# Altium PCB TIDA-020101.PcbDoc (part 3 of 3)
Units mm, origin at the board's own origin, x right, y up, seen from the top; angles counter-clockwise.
Board outline 55 x 55 mm, 4 copper layers (Top Layer 1, Top Layer, Bottom Layer, Bottom Layer 1), stack 1.647 mm thick; 151 components, 88 nets, 395 pads, 362 vias.
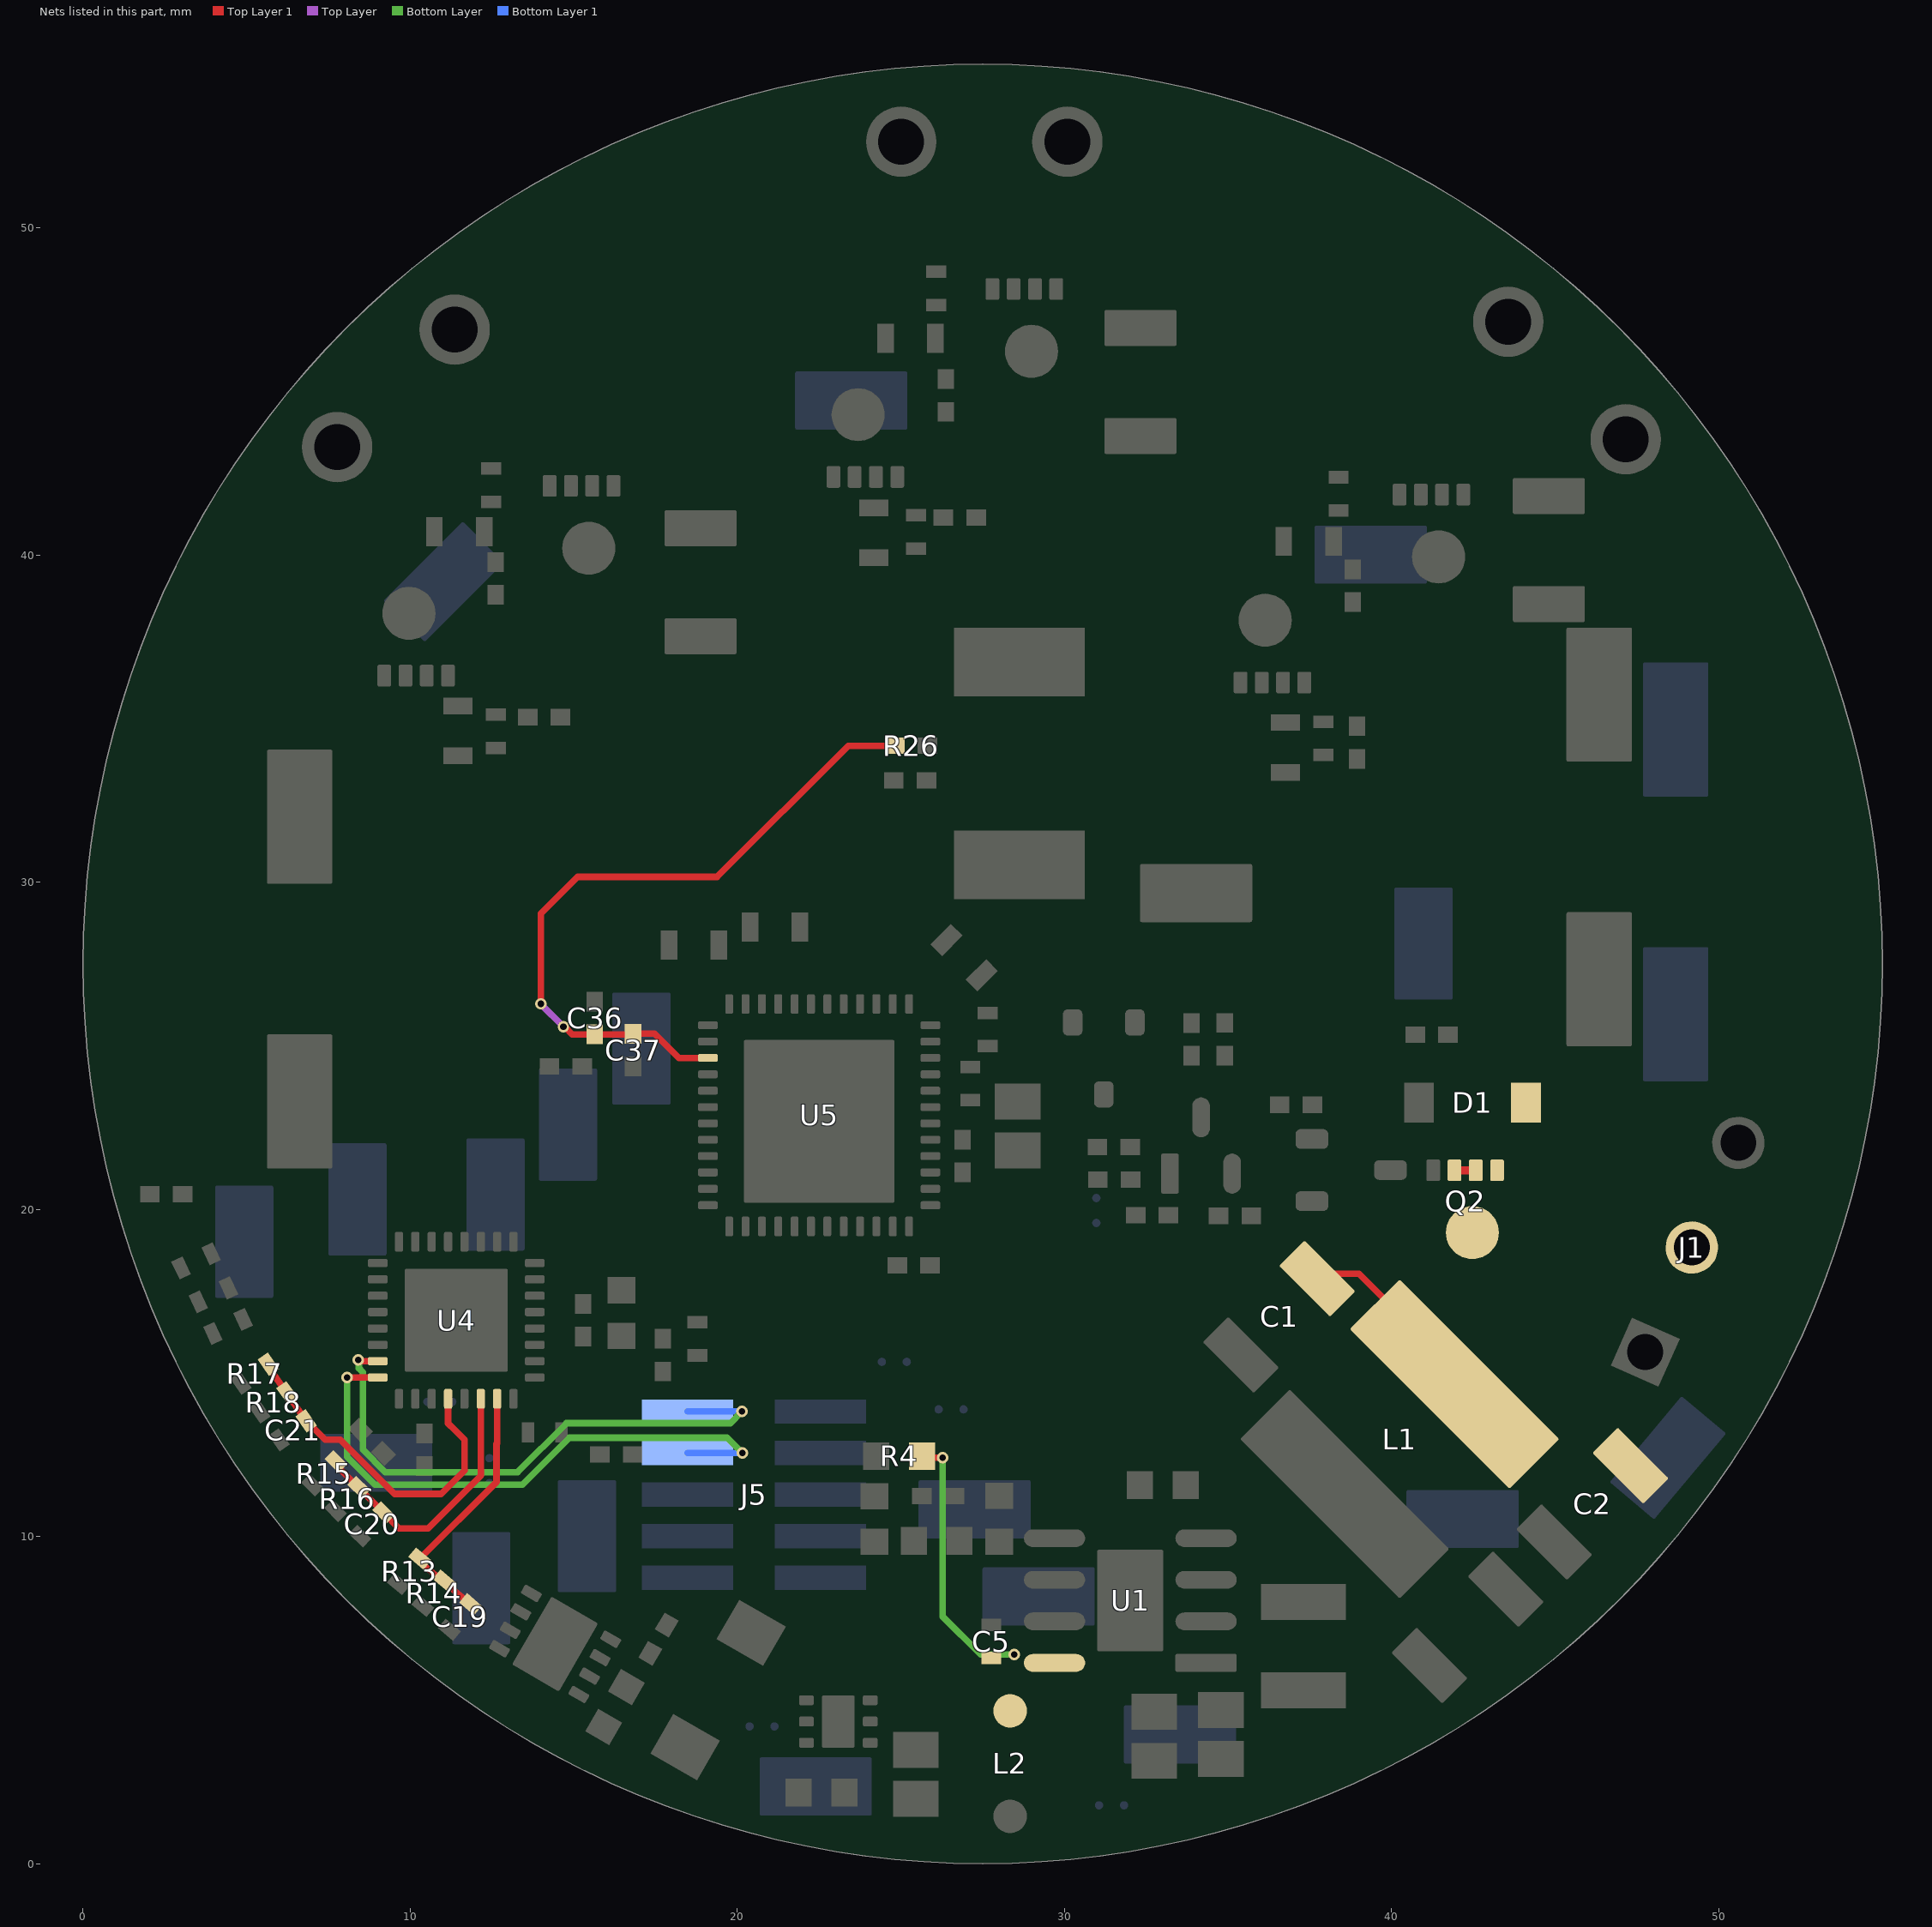
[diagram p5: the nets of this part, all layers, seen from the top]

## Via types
v1: diameter 0.6, hole 0.4, Top Layer 1 to Bottom Layer 1, tented both sides, 247 vias
v2: diameter 0.35, hole 0.2, Top Layer 1 to Bottom Layer 1, tented both sides, 92 vias
v3: diameter 0.5, hole 0.2, Top Layer 1 to Bottom Layer 1, tented both sides, 21 vias
v4: diameter 0.5, hole 0.2, Top Layer 1 to Bottom Layer 1, tented bottom, 2 vias

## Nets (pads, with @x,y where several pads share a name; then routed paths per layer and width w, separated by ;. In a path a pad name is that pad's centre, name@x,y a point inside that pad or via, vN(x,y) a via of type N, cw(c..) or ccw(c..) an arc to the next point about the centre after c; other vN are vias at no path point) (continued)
SPA: C36.1 C37.1 R26.2 U5.3 | length 21.5
  Top Layer 1 w0.2: v2(13.995,26.28) 13.995,29.036 15.121,30.162 19.385,30.162 23.389,34.166 R26.2@24.811,34.166 ; v2(14.683,25.58) 14.724,25.58 14.957,25.347 C36.1@15.64,25.347 16.794,25.347 C37.1@16.813,25.365 17.471,25.365 18.21,24.626 U5.3@19.1,24.626
  Top Layer w0.2: v2(13.995,26.28) 13.995,26.268 v2(14.683,25.58)
SW: C5.1 L2.1 R4.1 U1.8 | length 8.2
  Top Layer 1 w0.2: R4.1@25.642,12.455 25.692,12.405 v2(26.277,12.405)
  Bottom Layer w0.2: v2(26.277,12.405) 26.277,7.553 27.441,6.389 v2(28.459,6.389)
SWCLK: J5.4 U4.24 | length 18.3
  Top Layer 1 w0.2: v2(8.075,14.858) U4.24@9.007,14.858
  Bottom Layer w0.2: v2(8.075,14.858) 8.075,12.437 8.925,11.587 13.435,11.587 14.867,13.019 19.685,13.019 v2(20.155,12.55)
  Bottom Layer 1 w0.2: J5.4@18.474,12.55 v2(20.155,12.55)
SWDIO: J5.2 U4.23 | length 17.7
  Top Layer 1 w0.2: v2(8.407,15.395) 8.434,15.395 8.471,15.358 U4.23@9.007,15.358
  Bottom Layer w0.2: v2(8.407,15.395) 8.431,15.371 8.431,15.142 8.553,15.021 8.553,12.653 9.241,11.965 13.278,11.965 14.776,13.463 19.788,13.463 v2(20.145,13.82)
  Bottom Layer 1 w0.2: J5.2@18.474,13.82 v2(20.145,13.82)
VBATT: D1.1 J1.2 Q2.1 Q2.2 Q2.3 | length 0.7
  Top Layer 1 w0.254: Q2.3@41.921,21.193 Q2.2@42.571,21.193
VBATT_2: C1.2 C2.2 L1.1 Q2.5-6-7-8 | length 6.5
  Top Layer 1 w0.2: C1.2@37.483,17.642 C1.2@37.724,17.883 37.976,17.883 38.127,18.034 38.996,18.034 41.878,15.152 L1.1@42.597,15.152
VSENA: C19.1 R13.1 R14.2 U4.31 | length 8
  Top Layer 1 w0.2: C19.1@11.84,7.923 11.728,8.024 11.017,8.621 10.361,9.171 10.289,9.318 12.638,11.667 12.638,12.828 12.657,12.847 U4.31@12.657,14.208
VSENB: C20.1 R15.1 R16.2 U4.30 | length 8.3
  Top Layer 1 w0.2: R15.1@7.72,12.283 7.783,12.133 8.42,11.496 9.079,10.836 9.182,10.727 9.659,10.25 10.547,10.25 12.157,11.86 U4.30@12.157,14.208
VSENC: C21.1 R17.1 R18.2 U4.28 | length 10.5
  Top Layer 1 w0.2: R17.1@5.655,15.262 5.709,15.116 6.222,14.383 6.732,13.654 C21.1@6.816,13.53 ; C21.1@6.824,13.538 7.399,12.963 7.857,12.963 9.52,11.3 10.943,11.3 11.657,12.014 11.657,12.963 11.372,13.249 11.37,13.249 11.157,13.461 U4.28@11.157,14.208
pads on no net: J5.6 J5.8 U2.5 U2.7@23.086,3.894 U2.7@23.086,4.794 U4.1 U4.27 U5.31

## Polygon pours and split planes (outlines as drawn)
VBATT on Top Layer 1 "LAYER_1_NONET_P-001" (solid, pour order 45): 43.36,23.544 43.928,24.893 cw(c44.452,24.369) 44.452,25.11 45.086,25.11 46.4,24.677 48.9,22.284 48.942,22.244 cw(c48.628,21.93) 49.072,21.93 49.072,21.853 ccw(c49.629,21.854) 49.236,21.459 49.286,21.41 55.567,19.043 56,15.942 53.257,15.403 46.431,18.12 46.4,18.152 cw(c46.979,18.73) 46.161,18.73 46.161,18.764 ccw(c45.573,18.764) 45.989,19.179 44.913,19.587 44.596,19.904 cw(c44.943,20.251) 44.452,20.251 44.452,20.353 ccw(c44.136,20.353) 44.36,20.577 ccw(c44.081,20.299) 44.081,20.692 41.833,20.692 cw(c41.833,20.901) 41.686,20.753 cw(c41.902,20.97) 41.596,20.97 41.596,21.193 cw(c42.384,21.193) 41.827,21.75 42.97,22.893 ccw(c41.865,23.997)
+48V on Top Layer 1 "LAYER_1_NONET_P-001" (solid, pour order 86): 9.12,26.166 8.815,26.902 8.149,27.568 ccw(c7.177,25.222) 7.177,27.761 6.753,27.761 ccw(c6.749,26.23) 5.666,27.313 2.507,22.587 9.815,21.402 10.297,21.884 ccw(c9.931,22.251) 10.449,22.251 10.449,23.098 ccw(c10.13,23.098) 10.355,23.324
+48V on Top Layer 1 "LAYER_1_NONET_P-001" (solid, pour order 47): 41.844,9.386 ccw(c40.994,9.386) 41.451,10.102 36.949,14.605 36.676,14.605 34.78,12.709 34.78,11.834 35.541,11.073 35.541,9.447 35.272,9.177 33.573,9.177 33.304,8.908 33.304,7.058 33.663,6.699 37.245,6.733 38.442,6.733 42.044,3.131 44.445,5.531 42.246,7.73 cw(c43.208,8.697) 41.844,8.694 41.844,8.726
+12V on Top Layer 1 "LAYER_1_NONET_P-001" (solid, pour order 32): 38.114,26.108 38.202,26.196 40.077,26.196 40.151,26.121 40.151,25.313 40.078,25.239 38.207,25.239 38.109,25.336
GND on Top Layer 1 "LAYER_1_NONET_P-001" (solid, pour order 39): 17.473,39.281 16.733,38.541 16.733,35.867 17.769,34.831 19.691,34.831 21.122,36.262 21.122,38.097 19.961,39.258
AGND on Top Layer 1 "LAYER_1_NONET_P-001" (solid, pour order 62): -11.627,17.885 -11.627,-23.193 ccw(c-11.206,-23.173) -11.489,-23.485 ccw(c3.489,-2.75) 3.489,-28.33 ccw(c3.489,-2.75) 29.069,-2.75 ccw(c3.489,-2.75) 3.489,22.83 ccw(c3.489,-2.75)
GND on Top Layer 1 "LAYER_1_NONET_P-001" (solid, remove dead copper, pour order 88): 45.203,-4.723 62.209,12.283 ccw(c60.413,14.079) 62.953,14.079 62.953,48.975 ccw(c60.413,48.975) 62.209,50.771 52.197,60.783 ccw(c50.401,58.987) 50.401,61.527 8.161,61.527 ccw(c8.161,58.987) 6.365,60.783 -5.303,49.115 ccw(c-3.507,47.319) -6.047,47.319 -6.047,5.079 ccw(c-3.507,5.079) -5.303,3.283 2.703,-4.723
+12V on Top Layer 1 "LAYER_1_NONET_P-001" (solid, pour order 55): 26.145,4.502 23.836,4.502 23.836,3.554 24.572,2.818 25.968,2.818 26.33,3.179 26.33,4.317
+3V3_DRV on Top Layer 1 "LAYER_1_NONET_P-001" (solid, pour order 50): 25.597,21.497 27.278,21.497 27.381,21.599 27.61,21.643 27.731,21.95 27.731,22.395 27.656,22.471 26.565,22.471 26.515,22.422 26.515,22.214 26.055,21.754 25.597,21.754
VBATT_2 on Top Layer 1 "LAYER_1_NONET_P-001" (solid, pour order 46): 45.454,12.152 ccw(c44.962,11.66) 44.962,12.356 ccw(c44.962,11.645) 44.459,12.148 44.313,12.002 43.663,11.36 38.104,16.919 37.008,18.016 37.008,18.413 39.86,21.223 40.837,21.368 54.219,14.912 51.69,12.383 48.457,9.15
12V_Buck on Top Layer 1 "LAYER_1_NONET_P-001" (solid, pour order 44): 30.689,2.25 30.734,2.295 cw(c32.01,1.018) 32.01,2.823 33.472,2.823 ccw(c33.472,3.124) 33.685,2.912 ccw(c33.389,3.208) 33.808,3.208 33.808,3.375 33.848,3.415 cw(c34.122,3.14) 34.122,3.528 36.612,3.528 cw(c36.612,3.341) 36.745,3.473 cw(c36.659,3.388) 36.78,3.388 36.78,-0.5 27.897,-0.5 27.574,-0.178 27.574,2.25
SW on Top Layer 1 "LAYER_1_NONET_P-001" (solid, pour order 43): 31.35,5.682 31.375,5.656 cw(c31.161,5.442) 31.464,5.442 31.464,3.75 27.561,3.75 cw(c27.561,4.08) 27.232,4.08 27.232,6.435 cw(c27.36,6.435) 27.36,6.564 30.303,6.564 cw(c30.208,5.934) 30.583,6.449
MOTC on Top Layer 1 "LAYER_1_NONET_P-001" (solid, pour order 35): -1.25,36.81 8.56,36.81 11.433,36.81 12.084,37.461 12.084,39.27 11.616,39.738 11.616,41.838 11.802,42.024 13.69,42.024 14.077,42.411 14.4,42.411 14.552,42.259 14.552,41.762 14.849,41.465 20.612,41.465 22.437,43.29 22.437,48.791 14.916,56.311 10.785,56.311
GND_bridge on Top Layer 1 "LAYER_1_NONET_P-001" (solid, pour order 42): 36.773,36.008 36.773,36.39 36.585,36.578 34.63,36.578 34.379,36.828 34.38,41.096 34.08,41.395 26.809,41.395 26.321,41.883 26.321,42.597 25.726,43.192 21.963,43.192 20.166,41.395 20.166,36.742 20.222,36.686 20.181,36.645 8.835,36.645 8.835,32.393 10.231,30.997 18.89,30.997 23.68,35.786 31.532,35.786 32.276,35.043 32.276,32.454 33.005,31.724 38.571,31.724 39.239,32.392 39.239,33.967 38.939,34.266 38.515,34.266
GND on Top Layer 1 "LAYER_1_NONET_P-001" (solid, pour order 41): 43.048,42.51 43.048,40.469 43.945,39.572 46.3,39.572 46.804,40.076 46.804,42.475
GND on Top Layer 1 "LAYER_1_NONET_P-001" (solid, pour order 40): 31.288,45.523 30.548,44.783 30.548,42.109 31.281,41.376 34.293,41.376 34.937,42.021 34.937,44.339 33.776,45.5
+48V on Top Layer 1 "LAYER_1_NONET_P-001" (solid, pour order 38): 47.351,38.004 47.937,37.418 53.196,37.418 54.666,35.948 54.666,31.64 54.552,31.526 45.632,31.526 cw(c45.632,32.478) 44.958,31.805 44.906,31.857 ccw(c44.498,31.449) 44.498,32.026 43.837,32.026 ccw(c43.837,31.567) 43.512,31.892 43.318,31.698 cw(c42.914,32.084) 42.926,31.526 42.202,31.526 38.433,35.294 38.433,40.274 39.056,40.898 39.704,41.516 43.036,41.473 43.315,41.194 43.315,40.202 43.77,39.747 46.679,39.747 47.351,39.076
+48V on Top Layer 1 "LAYER_1_NONET_P-001" (solid, pour order 37): 20.95,39.805 20.95,41.137 20.19,41.897 13.527,41.983 12.879,41.364 12.263,40.748 12.263,37.247 12.044,37.028 12.044,35.847 12.278,35.613 16.155,35.613 16.932,36.39 16.932,38.474 17.55,39.092 20.237,39.092
+48V on Top Layer 1 "LAYER_1_NONET_P-001" (solid, pour order 36): 34.022,47.693 27.516,47.777 26.868,47.158 26.783,47.073 26.783,43.572 26.034,42.822 26.034,41.641 26.252,41.422 30.159,41.422 30.921,42.184 30.921,44.835 31.271,45.184 34.6,45.184 35.684,46.268
MOTB on Top Layer 1 "LAYER_1_NONET_P-001" (solid, pour order 34): 16.966,54.716 22.117,42.999 25.807,42.999 26.515,43.707 26.515,44.965 25.369,46.111 25.369,47.815 25.767,48.212 27.128,48.212 27.515,48.6 28.037,48.6 28.142,48.495 28.142,47.997 28.485,47.654 33.783,47.654 35.086,46.35 40.209,51.473 40.209,54.612 32.321,62.5 24.75,62.5
MOTA on Top Layer 1 "LAYER_1_NONET_P-001" (solid, pour order 33): 39.713,53.734 34.303,45.825 34.303,36.973 34.508,36.767 37.776,36.767 38.427,37.418 38.427,39.108 37.736,39.799 37.736,41.571 38.145,41.98 39.506,41.98 39.893,42.368 40.415,42.368 40.52,42.263 40.52,41.765 40.863,41.422 46.161,41.422 47.015,40.568 47.015,38.627 48.41,37.232 56.475,37.232 58.726,39.484 58.726,48.731 52.474,54.984 40.803,54.984
+48V on Bottom Layer 1 "LAYER_1_NONET_P-001" (solid, pour order 54): 30.716,27.086 30.716,32.234 30.001,32.949 23.354,32.949 19.656,29.25 18.087,29.25 9.837,21 7.832,21 6.093,19.753 1.747,15.59 0.93,16.406 cw(c2.023,17.5) 0.477,17.5 ccw(c0.477,17.819) 0.252,18.044 0.252,21.842 11.358,32.949 11.358,37.192 13.165,38.998 18.231,38.998 22.378,43.145 25.115,43.145 26.659,44.689 30.716,44.689 31.098,44.307 31.098,41.592 34.19,38.5 46.356,38.5 48.106,36.75 56.25,36.75 56.25,31.997 39.759,31.997 38.817,31.055 38.817,26.811 43.461,22.168 43.461,12.652 49.25,6.863 49.25,4.101 45.351,0.202 39.512,0.202 33.79,5.924 33.79,10.83 32.863,11.757 32.863,19.668 31.732,20.822 31.761,26.041
MOTC on Bottom Layer 1 "LAYER_1_NONET_P-001" (solid, pour order 67): 12.695,39.04 12.09,38.435 12.09,37.458 11.439,36.807 -1.243,36.807 10.792,56.308 14.923,56.308 22.443,48.788 22.443,43.287 18.197,39.04
GND on Bottom Layer 1 "LAYER_1_NONET_P-001" (solid, remove dead copper, pour order 69): 46.832,-4.25 63.838,12.756 ccw(c62.042,14.552) 64.582,14.552 64.582,49.448 ccw(c62.042,49.448) 63.838,51.244 53.826,61.256 ccw(c52.03,59.46) 52.03,62 9.79,62 ccw(c9.79,59.46) 7.994,61.256 -3.674,49.588 ccw(c-1.878,47.792) -4.418,47.792 -4.418,5.552 ccw(c-1.878,5.552) -3.674,3.756 4.332,-4.25
MOTB on Bottom Layer 1 "LAYER_1_NONET_P-001" (solid, pour order 66): 27.026,44.893 27.332,45.199 33.932,45.199 40.21,51.477 40.21,54.616 32.322,62.504 24.751,62.504 16.967,54.72 22.118,43.003 25.809,43.003 27.026,44.221
MOTA on Bottom Layer 1 "LAYER_1_NONET_P-001" (solid, pour order 65): 39.718,53.751 34.308,45.842 34.308,36.99 34.514,36.784 37.782,36.784 38.433,37.435 38.433,38.18 39.083,38.831 46.834,38.831 47.47,38.195 48.415,37.249 56.48,37.249 58.732,39.501 58.732,48.748 52.479,55.001 40.809,55.001
AGND on Bottom Layer 1 "LAYER_1_NONET_P-001" (solid, remove dead copper, pour order 57): -11.627,17.885 -11.627,-23.193 ccw(c-11.206,-23.173) -11.489,-23.485 ccw(c3.489,-2.75) 3.489,-28.33 ccw(c3.489,-2.75) 29.069,-2.75 ccw(c3.489,-2.75) 3.489,22.83 ccw(c3.489,-2.75)
+3V3 on Bottom Layer 1 "LAYER_1_NONET_P-001" (solid, pour order 59): 24.743,13.25 24.744,13.25 26.47,13.25 26.47,14.52 26.454,14.536 24.065,14.536 ccw(c24.065,14.056) 23.725,14.396 cw(c22.753,16.742) 22.753,14.202 20.995,14.202 ccw(c20.995,13.774) 20.692,14.077 ccw(c20.91,13.859) 20.602,13.859 20.602,13.615 ccw(c20.947,13.615) 20.703,13.37 20.831,13.242 20.949,13.25
+3V3 on Bottom Layer 1 "LAYER_1_NONET_P-001" (solid, pour order 51): 20.69,3.56 20.689,3.558 cw(c20.496,4.111) 20.105,3.72 19.969,3.857 cw(c20.661,4.549) 19.682,4.549 19.682,5.232 cw(c20.06,5.232) 19.793,5.5 cw(c20.114,5.179) 20.114,5.633 20.306,5.633 cw(c20.306,5.224) 20.595,5.513 cw(c20.356,5.274) 20.694,5.274 20.694,5.219
+12V on Bottom Layer 1 "LAYER_1_NONET_P-001" (solid, pour order 49): 31.374,2.333 27.961,2.333 26.33,3.964 26.33,4.317 26.145,4.502 23.836,4.502 23.836,3.554 24.572,2.818 25.968,2.818 26.54,2.246 26.54,-1.5 30.625,-1.5 31.375,-0.75
12V_Buck on Bottom Layer 1 "LAYER_1_NONET_P-001" (solid, pour order 48): 37.519,3.57 32.327,3.57 31.447,2.69 31.447,-0.5 37.271,-0.5 37.594,-0.178 37.519,-0.103
+12V on Top Layer "LAYER_1_NONET_P-001" (solid, pour order 53): 38.329,26.174 38.416,26.261 40.292,26.261 40.366,26.187 40.366,25.378 40.292,25.304 38.422,25.304 38.324,25.402
+48V on Top Layer "LAYER_1_NONET_P-001" (solid, pour order 63): 26.801,43.538 cw(c26.524,43.538) 26.524,43.261 26.468,43.261 ccw(c26.468,43.031) 26.238,43.031 26.238,41.876 ccw(c26.457,41.876) 26.457,41.658 29.331,41.658 ccw(c29.331,43.401) 31.075,43.401 ccw(c29.625,43.401) 29.625,44.85 27.005,44.85 ccw(c27.005,44.646) 26.801,44.646
MOTC on Top Layer "LAYER_1_NONET_P-001" (solid, pour order 85): -1.215,36.814 10.923,36.814 15.54,41.431 20.609,41.431 22.471,43.293 22.471,48.795 14.951,56.315 10.82,56.315
MOTB on Top Layer "LAYER_1_NONET_P-001" (solid, pour order 84): 26.515,45.181 26.812,45.478 34.213,45.478 40.209,51.473 40.209,54.612 32.321,62.5 24.75,62.5 16.966,54.716 22.117,42.999 25.807,42.999 26.515,43.707
MOTA on Top Layer "LAYER_1_NONET_P-001" (solid, pour order 79): 47.114,38.561 47.114,40.483 45.989,41.608 43.921,41.608 42.792,40.48 42.792,38.898 42.455,38.561 38.661,38.561 37.596,37.495 34.444,37.495 34.3,37.64 34.3,45.823 39.71,53.731 40.8,54.981 52.471,54.981 58.723,48.729 58.723,39.481 56.472,37.23 48.445,37.23
AGND on Top Layer "LAYER_1_NONET_P-001" (solid, pour order 78): -11.677,17.513 -11.677,-23.566 ccw(c-11.255,-23.546) -11.539,-23.858 ccw(c3.44,-3.123) 3.44,-28.702 ccw(c3.44,-3.123) 29.02,-3.123 ccw(c3.44,-3.123) 3.44,22.457 ccw(c3.44,-3.123)
GND on Top Layer "" (solid, pour order 87): 46.553,-6.447 65.75,12.75 65.75,47.862 53.112,60.5 5,60.5 -8,47.5 -8,4.75 -7,4.75 10.108,-6.069
+48V on Bottom Layer "LAYER_1_NONET_P-001" (solid, remove dead copper, pour order 82): 45.443,-3.64 62.449,13.366 ccw(c60.653,15.162) 63.193,15.162 63.193,50.058 ccw(c60.653,50.058) 62.449,51.854 52.437,61.866 ccw(c50.641,60.07) 50.641,62.61 8.401,62.61 ccw(c8.401,60.07) 6.605,61.866 -5.063,50.199 ccw(c-3.267,48.403) -5.807,48.403 -5.807,6.162 ccw(c-3.267,6.162) -5.063,4.366 2.943,-3.64
GND on Bottom Layer "LAYER_1_NONET_P-001" (solid, remove dead copper, pour order 83): 46.557,-3.75 63.563,13.256 ccw(c61.767,15.052) 64.307,15.052 64.307,49.948 ccw(c61.767,49.948) 63.563,51.744 53.551,61.756 ccw(c51.755,59.96) 51.755,62.5 9.514,62.5 ccw(c9.514,59.96) 7.718,61.756 -3.949,50.088 ccw(c-2.153,48.292) -4.693,48.292 -4.693,6.052 ccw(c-2.153,6.052) -3.949,4.256 4.057,-3.75
MOTC on Bottom Layer "LAYER_1_NONET_P-001" (solid, pour order 81): -1.215,36.814 10.923,36.814 13.125,39.016 18.194,39.016 22.471,43.293 22.471,48.795 14.951,56.315 10.82,56.315
MOTB on Bottom Layer "LAYER_1_NONET_P-001" (solid, pour order 80): 16.966,54.716 22.117,42.999 25.807,42.999 26.515,43.707 26.515,44.965 26.515,46.021 34.756,46.021 40.209,51.473 40.209,54.612 32.321,62.5 24.75,62.5
MOTA on Bottom Layer "LAYER_1_NONET_P-001" (solid, pour order 72): 39.71,53.731 34.3,45.823 34.3,37.64 34.444,37.495 37.596,37.495 38.661,38.561 47.114,38.561 48.445,37.23 56.472,37.23 58.723,39.481 58.723,48.729 52.471,54.981 40.8,54.981
AGND on Bottom Layer "LAYER_1_NONET_P-001" (solid, pour order 71): -11.615,17.885 -11.615,-23.194 ccw(c-11.194,-23.174) -11.478,-23.486 ccw(c3.501,-2.75) 3.501,-28.33 ccw(c3.501,-2.75) 29.081,-2.75 ccw(c3.501,-2.75) 3.501,22.829 ccw(c3.501,-2.75)
+3V3 on Bottom Layer "LAYER_1_NONET_P-001" (solid, pour order 64): 21.365,4.75 19.787,4.75 cw(c19.787,5.46) 19.285,4.958 15.315,11.073 14.611,12.085 cw(c14.925,12.4) 14.48,12.4 14.48,12.402 cw(c15.059,12.402) 14.65,12.811 14.858,13.019 21.547,13.019 ccw(c21.547,15.559) 23.344,13.763 24.154,14.574 cw(c24.351,14.378) 24.351,14.655 cw(c24.351,14.21) 24.666,14.525 24.734,14.457 cw(c24.335,14.057) 24.9,14.057 24.9,13.356 cw(c24.655,13.356) 24.828,13.182 21.778,5.36 cw(c20.729,5.691) 21.488,4.894

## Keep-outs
Top Layer 1:
  lines w0.254: 40.738,20.479 44.285,20.491 44.329,19.587 52.106,15.518
Keep-Out Layer:
  text ".Layer_Name" at 14.656,-21.806 h1

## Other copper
Top Layer 1:
  pour cut-out: 13.529,24.435 ccw(c13.581,24.487) 13.581,24.413 13.701,24.413 ccw(c13.697,24.48) 13.747,24.435 13.766,24.454 ccw(c13.67,24.55) 13.805,24.55 13.805,24.571 ccw(c13.663,24.575) 13.767,24.673 13.564,24.876 13.528,24.913 cw(c14.134,25.519) 13.277,25.519 13.277,29.227 cw(c13.996,29.229) 13.486,29.736 14.5,30.75 14.097,30.753 14.05,30.753 13.254,29.957 ccw(c13.912,29.276) 12.965,29.292 12.965,25.522 ccw(c14.232,25.523) 13.337,24.626
  pour cut-out: 29.32,31.507 29.32,35.851 27.862,35.851 27.862,34.511 27.754,34.403 25.066,34.403 25.066,33.411 25.066,32.591 27.693,32.591 cw(c27.693,32.284) 28,32.284 28,31.5
  text ".Layer_Name" at 14.656,-21.806 h1
Top Layer:
  pour cut-out: 15.5,25.25 15.5,27.036 ccw(c15.218,27.036) 15.218,27.318 13.286,27.318 ccw(c13.286,26.955) 12.923,26.955 12.923,25.185 ccw(c13.409,25.185) 13.409,24.699 15.268,24.699 ccw(c15.268,24.926) 15.495,24.926 ccw(c15.423,24.926) 15.423,24.998 13.455,24.998 cw(c13.455,25.262) 13.191,25.262 13.191,26.803 cw(c13.493,26.803) 13.493,27.105 15.037,27.105 cw(c15.037,26.812) 15.33,26.812 15.33,25.087 ccw(c15.366,25.087) 15.366,25.051 15.445,25.051 ccw(c15.445,25.109) 15.503,25.109
Bottom Layer:
  pour cut-out: 15.5,25.25 15.5,27.036 ccw(c15.218,27.036) 15.218,27.318 13.286,27.318 ccw(c13.286,26.955) 12.923,26.955 12.923,25.185 ccw(c13.409,25.185) 13.409,24.699 15.268,24.699 ccw(c15.268,24.926) 15.495,24.926 ccw(c15.423,24.926) 15.423,24.998 13.455,24.998 cw(c13.455,25.262) 13.191,25.262 13.191,26.803 cw(c13.493,26.803) 13.493,27.105 15.037,27.105 cw(c15.037,26.812) 15.33,26.812 15.33,25.087 ccw(c15.366,25.087) 15.366,25.051 15.445,25.051 ccw(c15.445,25.109) 15.503,25.109
Bottom Layer 1:
  pour cut-out: 15.5,25.25 15.5,27.036 ccw(c15.218,27.036) 15.218,27.318 13.286,27.318 ccw(c13.286,26.955) 12.923,26.955 12.923,25.185 ccw(c13.409,25.185) 13.409,24.699 15.268,24.699 ccw(c15.268,24.926) 15.495,24.926 ccw(c15.423,24.926) 15.423,24.998 13.455,24.998 cw(c13.455,25.262) 13.191,25.262 13.191,26.803 cw(c13.493,26.803) 13.493,27.105 15.037,27.105 cw(c15.037,26.812) 15.33,26.812 15.33,25.087 ccw(c15.366,25.087) 15.366,25.051 15.445,25.051 ccw(c15.445,25.109) 15.503,25.109
  text ".Layer_Name" at 14.656,-21.806 h1

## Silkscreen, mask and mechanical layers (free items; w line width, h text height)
Top Overlay:
  lines w0.15: 27.299,21.515 28.141,20.507 ; 27.476,23.876 28.172,24.682 ; 27.578,25.647 28.448,26.9
  text "B" at 21.051,51.473 h4
  text "A" at 39.505,49.035 h4 r315
  text "C" at 5.625,39.067 h4 r45
  text "GND" at 46.39,23.093 h1 r66
  text "+48V" at 44.854,19.459 h1 r71
  text "LIN" at 43.691,16.369 h1 r66
  text "TIDA-020101" at 25.348,13.765 h1.5
  text "rev.2.0" at 29.157,12.469 h1.5
  text ".Layer_Name" at 14.656,-21.806 h1
Bottom Overlay:
  lines w0.2: 16.779,8.585 16.779,13.975 ; 24.239,8.585 24.238,10.011 ; 24.239,13.155 24.243,12.371
  lines w0.254: 9.825,13.453 9.507,14.519 10.066,14.371
  text "MOTB" at 25.76,45.163 h1.75
  text "MOTC" at 17.277,40.065 h1.75
  text "MOTA" at 42.741,39.259 h1.75
  text "GND" at 42.661,25.084 h1.75
  text "DAC_OUT" at 10.424,22.383 h1
  text "FAULT_OUT" at 6.422,21.122 h1
  text "SDI" at 16.462,20.635 h1.75 r270
  text "DRV_3V3" at 30.293,19.973 h1.75
  text "SDO" at 14.23,17.403 h1.75 r270
  text "CLK" at 12.031,15.648 h1.75 r270
  text "LIN_INH" at 25.299,15.59 h1.25 r270
  text "'.PRJ_Number'.PCB_Rev" at 38.506,15.315 h1
  text "DRV_nSLEEP" at 20.68,14.96 h1.25 r270
  text "ISENS" at 9.22,14.024 h1.75
  text "+3V3" at 28.726,13.995 h1.25 r270
  text "LIN" at 48.222,13.844 h1.75 r50
  text "+48V" at 43.919,11.829 h1.75
  text "LIN_EN" at 13.43,9.948 h1.3 r270
  text "GND" at 30.696,7.61 h1.75
  text "GND" at 9.974,6.812 h1.75 r270
  text "Buck_out" at 38.002,5.202 h1.25
  text "nSCS" at 14.791,4.141 h1.75 r270
  text "+3.3V" at 19.859,3.59 h1.75
  text "+12V" at 30.548,1.204 h1.75
  text "LDO_out" at 24.463,0.534 h1.25 r270
  text ".Layer_Name" at 14.656,-21.806 h1
Top Paste:
  text ".Layer_Name" at 14.656,-21.806 h1
Bottom Paste:
  text ".Layer_Name" at 14.656,-21.806 h1
Top Solder:
  text ".Layer_Name" at 14.656,-21.806 h1
  text ".Layer_Name" at 14.656,-21.806 h1
Bottom Solder:
  text ".Layer_Name" at 14.656,-21.806 h1
Drill Guide:
  text ".Layer_Name" at 14.656,-21.806 h1
M1 Board Outline:
  circle w0.254: c27.5,27.5 r27.5
  text ".Layer_Name" at 14.656,-21.806 h1
M2 Board Dimensions:
  rectangle: 0,-6.985 3.175,-3.81
  rectangle: 3.175,-10.16 12.7,-6.985
  lines w0.178: 0,-6.985 25.4,-6.985 ; 3.175,-10.16 3.175,-3.81 ; 6.35,-10.16 6.35,-3.81 ; 12.7,-10.16 12.7,-3.81 ; 19.05,-10.16 19.05,-3.81 ; 0,-10.16 25.4,-10.16 25.4,-3.81 0,-3.81 0,-10.16
  text ".Layer_Name" at 14.656,-21.806 h1
M3 3D STEP Top:
  text ".Layer_Name" at 14.656,-21.806 h1
M4 3D STEP Bottom:
  text ".Layer_Name" at 14.656,-21.806 h1
M5 Assembly Top:
  lines w0.254: -7.417,-23.626 160.223,-23.626 ; -7.417,-18.462 160.274,-18.462 ; -7.417,-13.297 -7.417,-28.791 94.31,-28.791 160.274,-28.791 160.274,-13.297 -7.404,-13.297 -7.404,-28.791 32.614,-28.791 ; 55.194,-28.791 55.194,-13.297 ; 87.376,-18.462 87.376,-13.297 ; 108.712,-18.462 108.712,-13.297 ; 124.511,-28.956 124.511,-23.804
  text "COMPONENTS MARKED 'DNP' SHOULD NOT BE POPULATED." at 29.299,-8.09 h1
  text "ASSEMBLY VARIANT:" at 29.286,-11.024 h1
  text ".VariantName" at 55.601,-11.024 h1
  text "PCB VIEWED FROM TOP SIDE" at -5.804,-16.654 h1
  text "BOARD #:" at 57.099,-16.654 h1
  text ".PRJ_Number" at 70.955,-16.654 h1
  text "REV:" at 92.405,-16.654 h1
  text ".PCB_Rev" at 99.809,-16.654 h1
  text "SVN REV:" at 113.69,-16.654 h1
  text ".VersionControl_RevNumber" at 126.543,-16.654 h1
  text "TID #:" at 57.099,-21.819 h1
  text ".TID" at 70.955,-21.819 h1
  text "PLOT NAME =" at -5.804,-27.034 h1
  text ".plot_File_Name" at 14.656,-27.034 h1
  text "GENERATED    :" at 57.15,-27.034 h1
  text ".Print_Date" at 79.235,-27.034 h1
  text ".Print_Time" at 97.752,-27.034 h1
  text "TEXAS INSTRUMENTS" at 129.87,-27.034 h1
M6 Assembly Bottom:
  lines w0.254: -7.429,-18.474 160.261,-18.474 ; -7.379,-23.639 160.261,-23.639 ; 28.334,-28.969 28.334,-23.817 ; 44.133,-18.474 44.133,-13.31 ; 65.468,-18.474 65.468,-13.31 ; 97.65,-28.804 97.65,-13.31 ; 120.231,-28.804 160.249,-28.804 160.249,-13.31 -7.429,-13.31 -7.429,-28.804 58.534,-28.804 160.261,-28.804 160.261,-13.31
  text "COMPONENTS MARKED 'DNP' SHOULD NOT BE POPULATED." at 154.991,-8.077 h1
  text ".VariantName" at 128.473,-11.024 h1
  text "ASSEMBLY VARIANT:" at 154.864,-11.024 h1
  text ".VersionControl_RevNumber" at 26.302,-16.667 h1
  text "SVN REV:" at 39.154,-16.667 h1
  text ".PCB_Rev" at 53.035,-16.667 h1
  text "REV:" at 60.439,-16.667 h1
  text ".PRJ_Number" at 81.89,-16.667 h1
  text "BOARD #:" at 95.745,-16.667 h1
  text "PCB VIEWED FROM BOTTOM SIDE" at 158.648,-16.667 h1
  text ".TID" at 81.89,-21.831 h1
  text "TID #:" at 95.745,-21.831 h1
  text "TEXAS INSTRUMENTS" at 22.974,-27.047 h1
  text ".Print_Time" at 55.093,-27.047 h1
  text ".Print_Date" at 73.609,-27.047 h1
  text "GENERATED    :" at 95.694,-27.047 h1
  text ".plot_File_Name" at 138.189,-27.047 h1
  text "PLOT NAME =" at 158.648,-27.047 h1
M9 Title Sheet:
  drawing of 57 lines, arcs and shapes, not listed
  text "1" at 18.792,204.127 h1
  text "2" at 82.182,204.127 h1
  text "3" at 145.411,204.127 h1
  text "4" at 209.08,204.127 h1
  text "5" at 272.555,204.127 h1
  text "6" at 336.182,204.127 h1
  text "A" at -10.579,175.095 h1
  text "A" at 365.341,175.095 h1
  text "B" at -10.579,114.643 h1
  text "B" at 365.341,114.643 h1
  text "C" at -10.579,54.318 h1
  text "C" at 365.341,54.318 h1
  text "PROJECT TITLE:" at 288.125,7.048 h1
  text ".PRJ_Title" at 289.395,3.662 h1
  text "DESIGNED FOR:" at 288.125,-0.597 h1
  text ".PRJ_Customer" at 289.395,-4.153 h1
  text "D" at -10.579,-5.88 h1
  text "D" at 365.341,-5.88 h1
  text "FILE NAME:" at 288.125,-8.217 h1
  text ".PCB_File_Name_No_Path" at 289.395,-11.265 h1
  text "Texas Instruments (TI) and/or its licensors do not warrant the accuracy or completeness of this specification" at 161.9,-15.376 h1
  text "ENGINEER:" at 288.125,-15.583 h1
  text "LAYOUT BY:" at 326.352,-15.583 h1
  text "or any information contained therein. TI and/or its licensors do not warrant that this design will meet" at 160.757,-18.237 h1
  text ".PRJ_Engineer" at 289.395,-19.52 h1
  text ".PCB_Layout" at 327.635,-19.52 h1
  text "the specifications, will be suitable for your application or fit for any particular purpose, or will operate in" at 160.757,-21.099 h1
  text ".Layer_Name" at 14.656,-21.806 h1
  text "ALTIUM DESIGNER VERSION:" at 326.352,-23.457 h1
  text "an implementation. TI and/or its licensors do not warrant that the design is production worthy. You should" at 160.757,-23.961 h1
  text "completely validate and test your design implementation to confirm the system functionality for your application." at 161.9,-26.822 h1
  text ".print_Scale" at 289.395,-26.843 h1
  text ".Application_BuildNumber" at 327.635,-26.843 h1
  text "1" at 18.792,-32.093 h1
  text "2" at 82.182,-32.093 h1
  text "3" at 145.411,-32.093 h1
  text "4" at 209.08,-32.093 h1
  text "5" at 272.555,-32.093 h1
  text "6" at 336.182,-32.093 h1
M10 Fab Notes:
  drawing of 189 lines, arcs and shapes, not listed
  text "DESIGN INFORMATION" at 314.503,161.447 h1
  text "MIN. TRACK WIDTH:" at 298.131,158.091 h1
  text "8" at 325.976,158.091 h1
  text "MIL" at 329.907,158.091 h1
  text "7.874" at 321.75,155 h1
  text "MIN. CLEARANCE:" at 298.131,154.938 h1
  text "MIL" at 329.907,154.938 h1
  text "MIN. VIA PAD SIZE:" at 298.131,151.785 h1
  text "24" at 325.214,151.785 h1
  text "MIL" at 329.907,151.785 h1
  text "0.05mm (2MIL)" at 315.784,148.486 h1
  text "MINIMUM ANNULAR RING" at 289.769,148.277 h1
  text "EXTERNAL" at 333.768,148.277 h1
  text "PER" at 294.849,145.48 h1
  text "IPC-D-275 CLASS 2 LEVEL C" at 300.437,145.48 h1
  text "MIL, HOLES" at 338.238,142.928 h1
  text "+/-" at 328.27,142.709 h1
  text "+/-" at 349.961,142.709 h1
  text "REGISTRATION TOLERANCES:" at 289.769,142.682 h1
  text "METAL" at 320.243,142.682 h1
  text "5" at 334.879,142.683 h1
  text "3" at 356.037,142.683 h1
  text "MIL" at 358.99,142.682 h1
  text "HOLE SIZE TOLERANCE (UNLESS OTHERWISE SPECIFIED):" at 289.769,140.185 h1
  text "+/-" at 349.961,140.112 h1
  text "3" at 356.037,140.085 h1
  text "MIL" at 358.99,140.085 h1
  text "MATERIAL:" at 287.87,136.589 h1
  text "FR-4 High Tg" at 312.926,133.324 h1
  text "X" at 309.257,133.122 h1
  text "FR-4" at 298.563,133.007 h1
  text "OTHER" at 336.358,133.007 h1
  text "62 MIL (1.6mm) +/-10%" at 306.694,129.374 h1
  text "X" at 303.643,129.312 h1
  text "THICKNESS:" at 289.769,129.165 h1
  text "OTHER" at 339.33,129.165 h1
  text "TOLERANCE:" at 289.769,125.652 h1
  text "X" at 311.314,125.652 h1
  text "ANSI IPC-6012 TYPE 3 CLASS 2" at 315.836,125.652 h1
  text "OTHER +/-" at 315.835,121.989 h1
  text "BOW & TWIST:" at 289.769,118.302 h1
  text "X" at 311.314,118.302 h1
  text "ANSI IPC-6012 TYPE 3 CLASS 2" at 315.836,118.302 h1
  text "OTHER +/-" at 315.835,114.576 h1
  text "DRILLING:" at 287.87,111.258 h1
  text "NC_DRILL FILES" at 332.599,108.586 h1
  text "REFERENCE:" at 289.769,108.486 h1
  text "X" at 306.463,108.484 h1
  text "AS SHOWN" at 310.984,108.486 h1
  text "X" at 329.348,108.486 h1
  text "OTHER" at 340.168,104.873 h1
  text "PTH COPPER THICKNESS:" at 289.761,104.783 h1
  text "X" at 318.697,104.783 h1
  text "20-30 um" at 321.948,104.783 h1
  text "BOARD FINISH:" at 287.87,101.034 h1
  text "SILKSCREEN:" at 291.812,98.237 h1
  text "X" at 316.14,98.237 h1
  text "TOP" at 319.112,98.237 h1
  text "X" at 329.094,98.237 h1
  text "BOTTOM" at 332.091,98.237 h1
  text "SILKSCREEN COLOR:" at 291.812,94.295 h1
  text "X" at 316.115,94.295 h1
  text "WHITE" at 319.112,94.295 h1
  text "OTHER" at 332.091,94.295 h1
  text "X" at 319.442,90.652 h1
  text "GREEN" at 322.439,90.652 h1
  text "OTHER" at 338.136,90.652 h1
  text "SOLDER RESIST COLOR:" at 291.812,90.477 h1
  text "X" at 319.442,86.734 h1
  text "MATTE" at 322.439,86.734 h1
  text "SEMI-GLOSS" at 338.125,86.717 h1
  text "IMMERSION GOLD (ENIG)" at 314.819,82.345 h1
  text "ENEPIG" at 348.793,82.162 h1
  text "SURFACE FINISH:" at 287.87,82.136 h1
  text "X" at 310.298,82.136 h1
  text "IMM. TIN/SILVER OR EQUIV" at 296.24,78.649 h1
  text "OTHER" at 332.599,78.549 h1
  text "ARRAY/PANEL:" at 287.87,74.602 h1
  text "CUT AND TRIM PER M1 BOARD OUTLINE" at 314.819,74.393 h1
  text "N.C. ROUTE" at 314.819,70.94 h1
  text "X" at 332.295,70.94 h1
  text "V. SCORE" at 336.816,70.94 h1
  text "CERTIFICATION:" at 287.87,67.66 h1
  text "MATERIALS AND WORKMANSHIP FOR ALL PCBS" at 306.285,67.66 h1
  text "TO MEET OR EXCEED THE REQUIREMENTS OF:" at 306.285,65.271 h1
  text "X" at 297.078,62.003 h1
  text "ANSI IPC-A-600F CLASS ->" at 300.329,62.003 h1
  text "X" at 342.188,62.003 h1
  text "2" at 344.982,62.003 h1
  text "1" at 336.981,61.965 h1
  text "3" at 353.973,61.965 h1
  text "X" at 317.702,58.252 h1
  text "RoHS" at 320.953,58.252 h1
  text "OTHER" at 337.321,58.252 h1
  text "PER ORDER" at 347.407,58.252 h1
  text "ALL BOARDS MUST MEET OR EXCEED UL94-V0 REQUIREMENTS." at 288.569,54.345 h1
  text "PCB MUST BEAR THE UL94V-0 UL REGISTERED MATERIAL ID NUMBER" at 288.569,51.397 h1
  text "ADDITIONAL REQUIREMENTS:" at 287.87,47.094 h1
  text "MICROSECTION:" at 289.769,44.373 h1
  text "YES" at 312.775,44.373 h1
  text "REQUIRED" at 334.657,40.707 h1
  text "BARE BOARD ELEC. TEST:" at 289.769,40.634 h1
  text "NONE" at 322.935,40.634 h1
  text "X" at 331.66,40.634 h1
  text "PER ORDER" at 349.693,40.634 h1
  text "XX MIL VIAS REQUIRE NON-CONDUCTIVE FILL AND PLANARIZE" at 294.04,35.428 h1
  text "XX MIL VIAS REQUIRE CONDUCTIVE FILL AND PLANARIZE" at 294.243,32.787 h1
  text "OUTER XX MIL TRACES REQUIRE 50 OHM SINGLE-ENDED IMPEDANCE" at 294.218,28.637 h1
  text "LAYER 2 & 3 (INNER LAYERS) XX MIL WIDE, XX MIL SPACE / TRACES REQUIRE 100 OHM DIFFERENTIAL IMPEDANCE" at 294.015,22.65 h1
  text ".Layer_Name" at 14.656,-21.806 h1
M11 Gerber Information:
  lines w0.254: -7.417,-23.626 160.223,-23.626 ; -7.417,-18.462 160.274,-18.462 ; -7.417,-13.297 -7.417,-28.791 94.31,-28.791 160.274,-28.791 160.274,-13.297 -7.404,-13.297 -7.404,-28.791 32.614,-28.791 ; 55.194,-28.791 55.194,-13.297 ; 87.376,-18.462 87.376,-13.297 ; 108.712,-18.462 108.712,-13.297 ; 124.511,-28.956 124.511,-23.804
  text "ALL ARTWORK VIEWED FROM TOP SIDE" at -5.804,-16.654 h1
  text "BOARD #:" at 57.099,-16.654 h1
  text ".PRJ_Number" at 70.955,-16.654 h1
  text "REV:" at 92.405,-16.654 h1
  text ".PCB_Rev" at 99.809,-16.654 h1
  text "SVN REV:" at 113.69,-16.654 h1
  text ".VersionControl_RevNumber" at 126.543,-16.654 h1
  text "LAYER NAME =" at -5.804,-21.806 h1
  text "TID #:" at 57.099,-21.819 h1
  text ".TID" at 70.955,-21.819 h1
  text "PLOT NAME =" at -5.804,-27.034 h1
  text ".plot_File_Name" at 14.656,-27.034 h1
  text "GENERATED    :" at 57.15,-27.034 h1
  text ".Print_Date" at 79.235,-27.034 h1
  text ".Print_Time" at 97.752,-27.034 h1
  text "TEXAS INSTRUMENTS" at 129.87,-27.034 h1
M12 Stackup:
  drawing of 295 lines, arcs and shapes, not listed
  text "Layer" at 248.945,200.809 h1
  text "Name" at 255.951,200.809 h1
  text "Material" at 271.621,200.809 h1
  text "Thickness" at 286.126,200.809 h1
  text "Constant" at 297.131,200.809 h1
  text "Board Layer Stack" at 306.803,200.809 h1
  text "Top Overlay" at 255.951,198.81 h1
  text "Top Solder" at 255.951,196.81 h1
  text "Solder Resist" at 271.621,196.81 h1
  text "0.40mil" at 286.126,196.81 h1
  text "3.5" at 297.131,196.81 h1
  text "1" at 248.945,194.81 h1
  text "Top Layer 1" at 255.951,194.81 h1
  text "CF-004" at 271.621,194.81 h1
  text "2.76mil" at 286.126,194.81 h1
  text "Dielectric 1" at 255.951,192.81 h1
  text "PP-006" at 271.621,192.81 h1
  text "7.99mil" at 286.126,192.81 h1
  text "4.1" at 297.131,192.81 h1
  text "2" at 248.945,190.81 h1
  text "Top Layer" at 255.951,190.81 h1
  text "1.40mil" at 286.126,190.81 h1
  text "Dielectric1" at 255.951,188.81 h1
  text "FR-4 High Tg" at 271.621,188.81 h1
  text "40.55mil" at 286.126,188.81 h1
  text "4.8" at 297.131,188.81 h1
  text "3" at 248.945,186.81 h1
  text "Bottom Layer" at 255.951,186.81 h1
  text "1.40mil" at 286.126,186.81 h1
  text "Dielectric 2" at 255.951,184.81 h1
  text "PP-006" at 271.621,184.81 h1
  text "7.99mil" at 286.126,184.81 h1
  text "4.1" at 297.131,184.81 h1
  text "4" at 248.945,182.81 h1
  text "Bottom Layer 1" at 255.951,182.81 h1
  text "CF-004" at 271.621,182.81 h1
  text "2.76mil" at 286.126,182.81 h1
  text "Bottom Solder" at 255.951,180.81 h1
  text "Solder Resist" at 271.621,180.81 h1
  text "0.40mil" at 286.126,180.81 h1
  text "3.5" at 297.131,180.81 h1
  text "Bottom Overlay" at 255.951,178.81 h1
  text ".Layer_Name" at 14.656,-21.806 h1
M13 Component Bodies Top:
  text ".Layer_Name" at 14.656,-21.806 h1
M14 Component Bodies Bottom:
  text ".Layer_Name" at 14.656,-21.806 h1
M15 Courtyards Top:
  text ".Layer_Name" at 14.656,-21.806 h1
M16 Courtyards Bottom:
  text ".Layer_Name" at 14.656,-21.806 h1
Drill Drawing:
  lines w0.254: 135.126,78.511 135.126,78.741 135.356,78.971 135.126,79.201 135.126,79.431 135.356,79.431 135.586,79.201 135.816,79.431 136.046,79.431 136.046,79.201 135.816,78.971 136.046,78.741 136.046,78.511 135.816,78.511 135.586,78.741 135.356,78.511 135.126,78.511 ; 135.126,80.581 135.586,80.811 136.046,80.581 135.816,81.041 136.046,81.501 135.586,81.271 135.126,81.501 135.356,81.041 135.126,80.581 ; 135.126,82.881 135.356,82.881 135.356,82.651 135.816,82.651 135.816,82.881 136.046,82.881 136.046,83.341 135.816,83.341 135.816,83.571 135.356,83.571 135.356,83.341 135.126,83.341 135.126,82.881 ; 135.126,84.721 136.046,84.721 136.046,85.641 135.126,85.641 135.126,84.721
  lines w0.305: 134.264,77.89 189.433,77.89 ; 134.264,86.17 189.433,86.17 ; 139.893,75.82 139.893,88.24 ; 145.425,75.82 145.425,88.24 ; 156.033,75.82 156.033,88.24 ; 160.351,75.82 160.351,88.24 ; 166.602,75.82 166.602,88.24 ; 179.994,75.82 179.994,88.24 ; 134.264,75.82 189.433,75.82 189.433,88.24 134.264,88.24 134.264,75.82
  text "Symbol" at 135.506,86.791 h1.2
  text "Quantity" at 140.514,86.791 h1.2
  text "Finished Hole Size" at 146.046,86.791 h1.2
  text "Plated" at 156.654,86.791 h1.2
  text "Hole Type" at 160.972,86.791 h1.2
  text "Drill Layer Pair" at 167.223,86.791 h1.2
  text "Hole Tolerance" at 180.615,86.791 h1.2
  text "115" at 140.514,84.721 h1
  text "7.87mil (0.200mm)" at 146.046,84.721 h1
  text "PTH" at 156.654,84.721 h1
  text "Round" at 160.972,84.721 h1
  text "Top Layer 1 - Bottom Layer 1" at 167.223,84.721 h1
  text "247" at 140.514,82.651 h1
  text "15.75mil (0.400mm)" at 146.046,82.651 h1
  text "PTH" at 156.654,82.651 h1
  text "Round" at 160.972,82.651 h1
  text "Top Layer 1 - Bottom Layer 1" at 167.223,82.651 h1
  text "3" at 140.514,80.581 h1
  text "43.31mil (1.100mm)" at 146.046,80.581 h1
  text "PTH" at 156.654,80.581 h1
  text "Round" at 160.972,80.581 h1
  text "Top Layer 1 - Bottom Layer 1" at 167.223,80.581 h1
  text "6" at 140.514,78.511 h1
  text "55.12mil (1.400mm)" at 146.046,78.511 h1
  text "PTH" at 156.654,78.511 h1
  text "Round" at 160.972,78.511 h1
  text "Top Layer 1 - Bottom Layer 1" at 167.223,78.511 h1
  text "371 Total" at 140.514,76.441 h1
  text ".Layer_Name" at 14.656,-21.806 h1
M17 Embedded Cavity:
  text ".Layer_Name" at 14.656,-21.806 h1
M18 Embedded Assembly:
  text ".Layer_Name" at 14.656,-21.806 h1
M19 Embedded Keepout:
  text ".Layer_Name" at 14.656,-21.806 h1

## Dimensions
0,-10.16 to 25.4,-10.16 on M2 Board Dimensions
0,0 to 27.5,55 on M2 Board Dimensions
0,0 to 55,27.5 on M2 Board Dimensions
